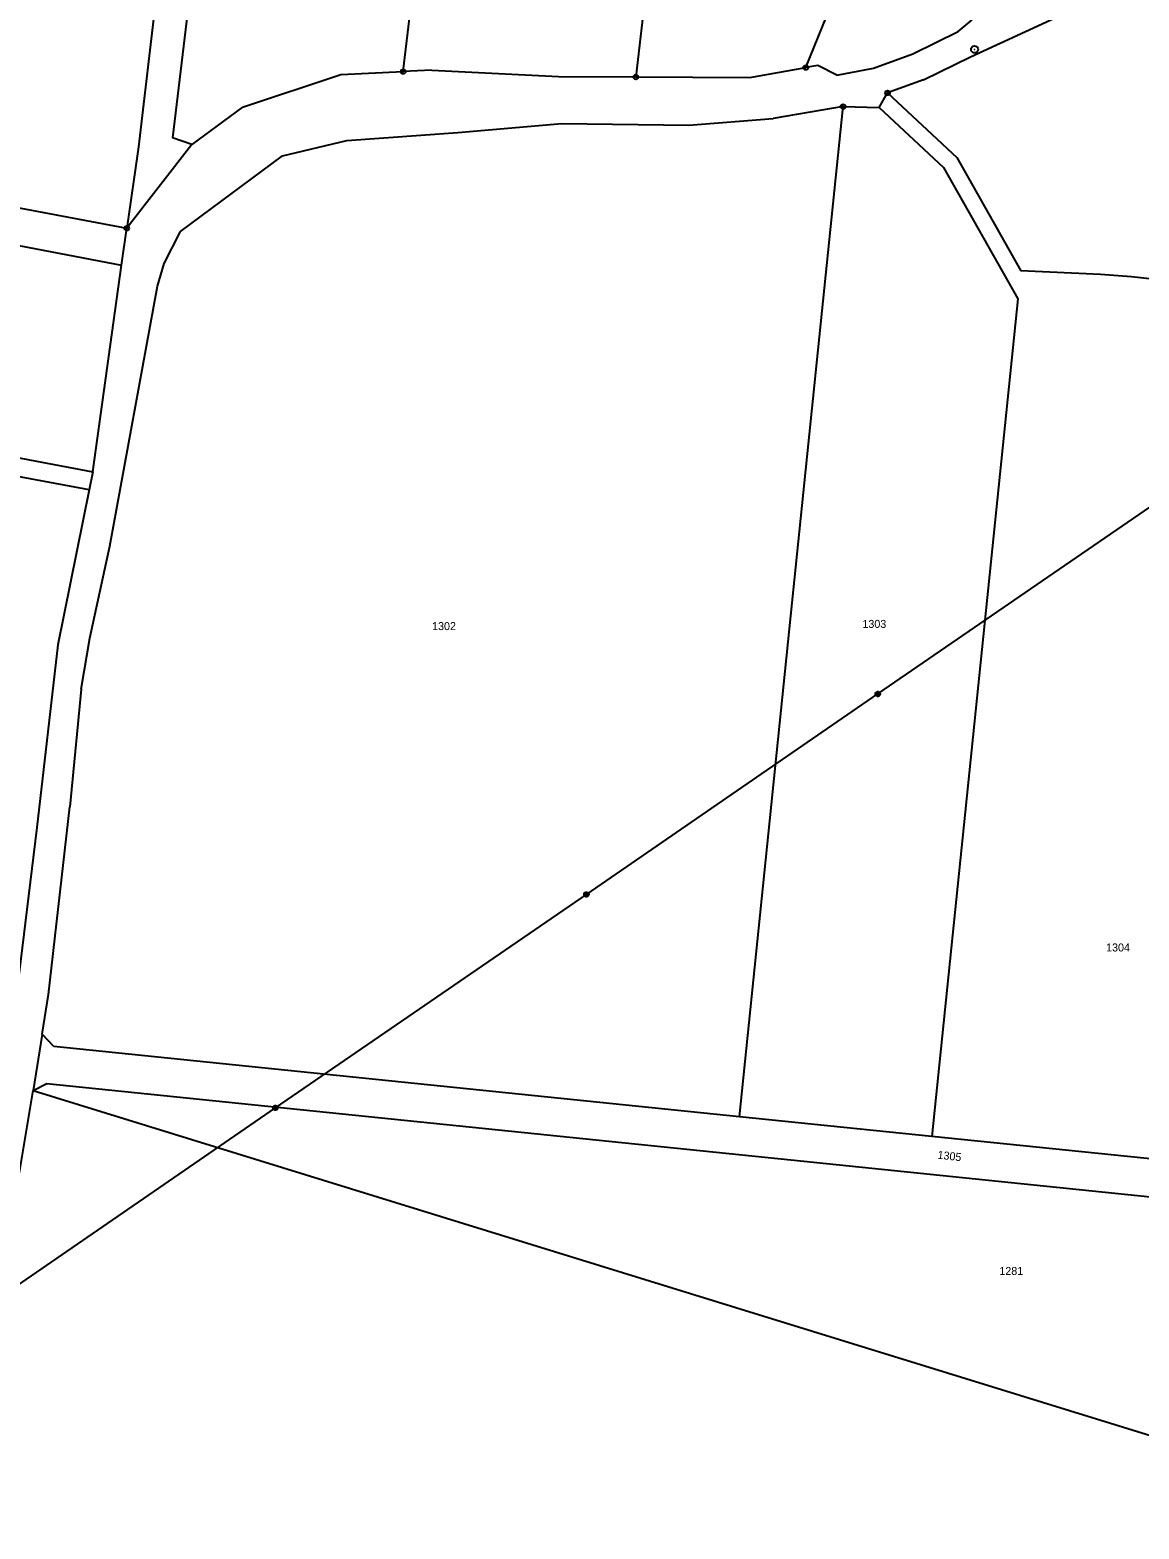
# Model space of a CAD drawing. Extents: x -796130 to -793145, y -1109506 to -1106267.
# Drawn here: x -794845 to -794609.3, y -1108148.6 to -1107830.1 of the extents above; entities that cross this region are included whole.
import ezdxf

# ---------------------------------------------------------------- set-up
doc = ezdxf.new("R2010")
doc.units = 0
for name, color, linetype in [('Vrstva 1', 7, 'Continuous'), ('Vrstva 12', 7, 'Continuous'), ('Vrstva 14', 7, 'Continuous'), ('Vrstva 26', 7, 'Continuous'), ('Vrstva 28', 7, 'Continuous')]:
    doc.layers.add(name, color=color, linetype=linetype)

msp = doc.modelspace()

# ---------------------------------------------------------------- linework, layer by layer
at = {"layer": 'Vrstva 1'}
for p, q in [((-794812.44, -1107774.92), (-794821.91, -1107854.92)), ((-794805.49, -1107775.74), (-794814.66, -1107853)), ((-794765.64, -1107838.94), (-794759.22, -1107784.77)), ((-794711.11, -1107796.1), (-794716.25, -1107840.09)), ((-794680.15, -1107838.09), (-794664.25, -1107798.84)), ((-794647.75, -1107830.4), (-794644.79, -1107827.95)), ((-794645.15, -1107835.81), (-794627.11, -1107827.53)), ((-794657.41, -1107835.14), (-794647.75, -1107830.4)), ((-794665.73, -1107838.23), (-794657.41, -1107835.14)), ((-794692.02, -1107840.21), (-794680.15, -1107838.09)), ((-794677.55, -1107837.62), (-794680.15, -1107838.09)), ((-794673.5, -1107839.72), (-794677.55, -1107837.62)), ((-794673.5, -1107839.72), (-794665.73, -1107838.23)), ((-794655.14, -1107840.69), (-794645.15, -1107835.81)), ((-794799.8, -1107846.5), (-794778.91, -1107839.53)), ((-794778.91, -1107839.53), (-794765.64, -1107838.94)), ((-794759.55, -1107838.67), (-794765.64, -1107838.94)), ((-794759.55, -1107838.67), (-794732.7, -1107839.95)), ((-794732.7, -1107839.95), (-794716.25, -1107840.09)), ((-794716.25, -1107840.09), (-794692.02, -1107840.21)), ((-794655.14, -1107840.69), (-794662.76, -1107843.48)), ((-794664.55, -1107846.6), (-794662.76, -1107843.48)), ((-794662.76, -1107843.48), (-794648.05, -1107857.22)), ((-794799.8, -1107846.5), (-794810.6, -1107854.4)), ((-794672.21, -1107846.37), (-794687.08, -1107848.91)), ((-794683.03, -1107951.84), (-794672.21, -1107846.37)), ((-794672.21, -1107846.37), (-794664.55, -1107846.6)), ((-794664.55, -1107846.6), (-794650.89, -1107859.33)), ((-794986.27, -1107849.69), (-794825.49, -1107880.04)), ((-794754.09, -1107851.86), (-794731.97, -1107849.97)), ((-794731.97, -1107849.97), (-794705.01, -1107850.35)), ((-794705.01, -1107850.35), (-794687.08, -1107848.91)), ((-794810.6, -1107854.4), (-794824.39, -1107872.24)), ((-794810.6, -1107854.4), (-794814.66, -1107853)), ((-794791.28, -1107856.82), (-794777.63, -1107853.57)), ((-794777.63, -1107853.57), (-794754.09, -1107851.86)), ((-794821.91, -1107854.92), (-794824.39, -1107872.24)), ((-794813, -1107872.95), (-794791.28, -1107856.82)), ((-794648.05, -1107857.22), (-794634.44, -1107881.29)), ((-794650.89, -1107859.33), (-794635.06, -1107887.21)), ((-794883.59, -1107861.08), (-794824.39, -1107872.24)), ((-794825.49, -1107880.04), (-794824.39, -1107872.24)), ((-794816.47, -1107879.75), (-794813, -1107872.95)), ((-794817.85, -1107884.55), (-794816.47, -1107879.75)), ((-794831.59, -1107923.99), (-794825.49, -1107880.04)), ((-794617.48, -1107882.05), (-794634.44, -1107881.29)), ((-794610.94, -1107882.54), (-794617.48, -1107882.05)), ((-794589.78, -1107884.99), (-794610.94, -1107882.54)), ((-794828, -1107939.75), (-794817.85, -1107884.55)), ((-794635.06, -1107887.21), (-794653.33, -1108065.2)), ((-794832.37, -1107927.84), (-795010.24, -1107894.34)), ((-794993.37, -1107893.47), (-794831.59, -1107923.99)), ((-794831.59, -1107923.99), (-794832.37, -1107927.84)), ((-794832.37, -1107927.84), (-794839.04, -1107960.75)), ((-794832.24, -1107959.29), (-794828, -1107939.75)), ((-794694.24, -1108061), (-794683.03, -1107951.84)), ((-794834.1, -1107970.16), (-794832.24, -1107959.29)), ((-794839.04, -1107960.75), (-794843.53, -1107999.53)), ((-794834.1, -1107970.16), (-794836.47, -1107995.13)), ((-794841.05, -1108035.01), (-794836.47, -1107995.13)), ((-794843.53, -1107999.53), (-794848.72, -1108042.54)), ((-794842.38, -1108043.45), (-794841.05, -1108035.01)), ((-794842.38, -1108043.45), (-794844.27, -1108055.42)), ((-794839.91, -1108046.05), (-794842.38, -1108043.45)), ((-794694.24, -1108061), (-794839.91, -1108046.05)), ((-794844.27, -1108055.42), (-794841.39, -1108053.94)), ((-794841.39, -1108053.94), (-794683.27, -1108070.18)), ((-794847.7, -1108075.8), (-794844.27, -1108055.42)), ((-794844.27, -1108055.42), (-794695.01, -1108101.53)), ((-794653.33, -1108065.2), (-794694.24, -1108061)), ((-794535.24, -1108077.32), (-794653.33, -1108065.2)), ((-794683.27, -1108070.18), (-794536.14, -1108085.28)), ((-794695.01, -1108101.53), (-794542.64, -1108148.6))]:
    msp.add_line(p, q, dxfattribs=at)
at = {"layer": 'Vrstva 12'}
for p, q in [((-794664.83, -1107971.18), (-794601.41, -1107927.64)), ((-794726.74, -1108013.76), (-794664.83, -1107971.18)), ((-794792.81, -1108059.11), (-794726.74, -1108013.76)), ((-794852.88, -1108100.44), (-794792.81, -1108059.11))]:
    msp.add_line(p, q, dxfattribs=at)
at = {"layer": 'Vrstva 26'}
for p, q in [((-794665.33, -1107971.08), (-794665.23, -1107970.88)), ((-794665.33, -1107971.28), (-794665.33, -1107971.08)), ((-794665.23, -1107971.48), (-794665.33, -1107971.28)), ((-794665.23, -1107970.88), (-794665.13, -1107970.78)), ((-794665.13, -1107971.58), (-794665.23, -1107971.48)), ((-794665.13, -1107970.78), (-794664.93, -1107970.68)), ((-794665.13, -1107970.98), (-794665.13, -1107971.38)), ((-794665.13, -1107971.38), (-794664.93, -1107971.48)), ((-794664.93, -1107971.68), (-794665.13, -1107971.58)), ((-794664.93, -1107970.68), (-794664.73, -1107970.68)), ((-794664.93, -1107971.48), (-794664.93, -1107970.88)), ((-794664.93, -1107970.88), (-794664.73, -1107970.88)), ((-794664.73, -1107971.68), (-794664.93, -1107971.68)), ((-794664.73, -1107970.68), (-794664.53, -1107970.78)), ((-794664.73, -1107970.88), (-794664.73, -1107971.48)), ((-794664.73, -1107971.48), (-794664.53, -1107971.38)), ((-794664.53, -1107971.58), (-794664.73, -1107971.68)), ((-794664.53, -1107970.78), (-794664.43, -1107970.88)), ((-794664.53, -1107971.38), (-794664.53, -1107970.98)), ((-794664.43, -1107971.48), (-794664.53, -1107971.58)), ((-794664.43, -1107970.88), (-794664.33, -1107971.08)), ((-794664.33, -1107971.28), (-794664.43, -1107971.48)), ((-794664.33, -1107971.08), (-794664.33, -1107971.28)), ((-794727.24, -1108013.66), (-794727.14, -1108013.46)), ((-794727.24, -1108013.86), (-794727.24, -1108013.66)), ((-794727.14, -1108013.46), (-794727.04, -1108013.36)), ((-794727.04, -1108013.36), (-794726.84, -1108013.26)), ((-794727.04, -1108013.56), (-794727.04, -1108013.96)), ((-794726.84, -1108013.26), (-794726.64, -1108013.26)), ((-794726.84, -1108014.06), (-794726.84, -1108013.46)), ((-794726.84, -1108013.46), (-794726.64, -1108013.46)), ((-794726.64, -1108013.26), (-794726.44, -1108013.36)), ((-794726.64, -1108013.46), (-794726.64, -1108014.06)), ((-794726.44, -1108013.36), (-794726.34, -1108013.46)), ((-794726.44, -1108013.96), (-794726.44, -1108013.56)), ((-794726.34, -1108013.46), (-794726.24, -1108013.66)), ((-794726.24, -1108013.66), (-794726.24, -1108013.86)), ((-794727.14, -1108014.06), (-794727.24, -1108013.86)), ((-794727.04, -1108014.16), (-794727.14, -1108014.06)), ((-794727.04, -1108013.96), (-794726.84, -1108014.06)), ((-794726.84, -1108014.26), (-794727.04, -1108014.16)), ((-794726.64, -1108014.26), (-794726.84, -1108014.26)), ((-794726.64, -1108014.06), (-794726.44, -1108013.96)), ((-794726.44, -1108014.16), (-794726.64, -1108014.26)), ((-794726.34, -1108014.06), (-794726.44, -1108014.16)), ((-794726.24, -1108013.86), (-794726.34, -1108014.06)), ((-794793.31, -1108059.01), (-794793.21, -1108058.81)), ((-794793.31, -1108059.21), (-794793.31, -1108059.01)), ((-794793.21, -1108059.41), (-794793.31, -1108059.21)), ((-794793.21, -1108058.81), (-794793.11, -1108058.71)), ((-794793.11, -1108059.51), (-794793.21, -1108059.41)), ((-794793.11, -1108058.71), (-794792.91, -1108058.61)), ((-794793.11, -1108058.91), (-794793.11, -1108059.31)), ((-794793.11, -1108059.31), (-794792.91, -1108059.41)), ((-794792.91, -1108059.61), (-794793.11, -1108059.51)), ((-794792.91, -1108058.61), (-794792.71, -1108058.61)), ((-794792.91, -1108059.41), (-794792.91, -1108058.81)), ((-794792.91, -1108058.81), (-794792.71, -1108058.81)), ((-794792.71, -1108059.61), (-794792.91, -1108059.61)), ((-794792.71, -1108058.61), (-794792.51, -1108058.71)), ((-794792.71, -1108058.81), (-794792.71, -1108059.41)), ((-794792.71, -1108059.41), (-794792.51, -1108059.31)), ((-794792.51, -1108059.51), (-794792.71, -1108059.61)), ((-794792.51, -1108058.71), (-794792.41, -1108058.81)), ((-794792.51, -1108059.31), (-794792.51, -1108058.91)), ((-794792.41, -1108059.41), (-794792.51, -1108059.51)), ((-794792.41, -1108058.81), (-794792.31, -1108059.01)), ((-794792.31, -1108059.21), (-794792.41, -1108059.41)), ((-794792.31, -1108059.01), (-794792.31, -1108059.21))]:
    msp.add_line(p, q, dxfattribs=at)
at = {"layer": 'Vrstva 28'}
for centre, radius in [((-794644.27, -1107834.24), 0.75), ((-794644.27, -1107834.24), 0.01), ((-794765.64, -1107838.94), 0.5), ((-794680.15, -1107838.09), 0.5), ((-794680.15, -1107838.09), 0.01), ((-794765.64, -1107838.94), 0.01), ((-794716.25, -1107840.09), 0.5), ((-794716.25, -1107840.09), 0.01), ((-794662.76, -1107843.48), 0.5), ((-794662.76, -1107843.48), 0.01), ((-794672.21, -1107846.37), 0.5), ((-794672.21, -1107846.37), 0.01), ((-794824.39, -1107872.24), 0.5), ((-794824.39, -1107872.24), 0.01)]:
    msp.add_circle(centre, radius, dxfattribs=at)

# ---------------------------------------------------------------- texts
at = {"layer": 'Vrstva 14'}
for s, p in [('1302', (-794759.519, -1107957.61)), ('1303', (-794668.089, -1107957.14)), ('1304', (-794616.315, -1108025.89)), ('1281', (-794638.993, -1108094.62))]:
    msp.add_text(s, height=1.7, dxfattribs=at).set_placement(p)
msp.add_text('1305', height=1.7, rotation=353.7, dxfattribs=at).set_placement((-794652.192, -1108069.902))

doc.saveas('drawing.dxf')
